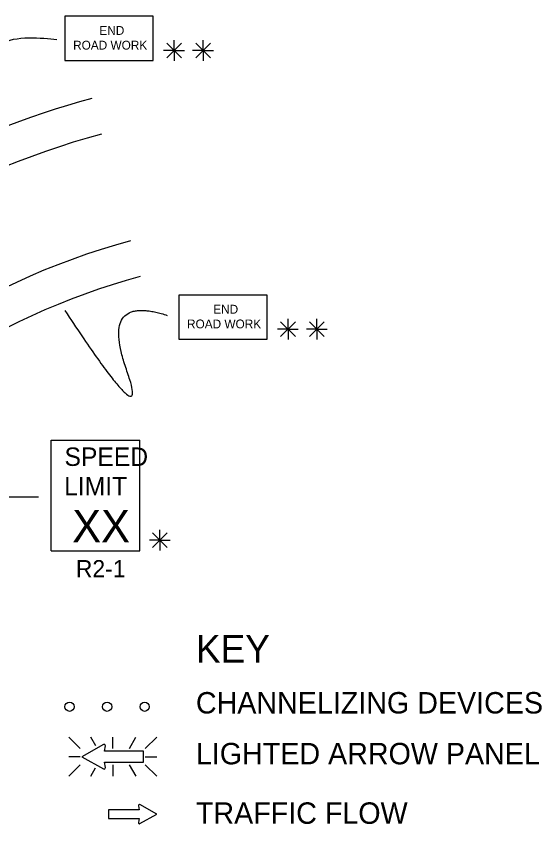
# Model space of a CAD drawing. Extents: x 16728 to 19508, y 5553 to 7079.
# Drawn here: x 17179.3 to 17407.4, y 6484.5 to 6837.4 of the extents above; entities that cross this region are included whole.
import ezdxf

# ---------------------------------------------------------------- set-up
doc = ezdxf.new("R2010")
doc.units = 0
for name, color, linetype in [('MT_SCRATCH_LEVEL_E', 7, 'Continuous'), ('PAVT_EDGE_EX', 7, 'Continuous'), ('TRAFFIC_SIGNS_PR', 7, 'Continuous'), ('TYPICAL_TEXT_DIMEN_EX', 7, 'Continuous'), ('TYPICAL_TEXT_DIMEN_PR', 7, 'Continuous')]:
    doc.layers.add(name, color=color, linetype=linetype)

msp = doc.modelspace()

# ---------------------------------------------------------------- linework, layer by layer
at = {"layer": 'MT_SCRATCH_LEVEL_E'}
for p, q in [((17232.32, 6494.92), (17232.64, 6493.15)), ((17240.25, 6491.29), (17233.01, 6495.4)), ((17232.64, 6493.15), (17219.38, 6493.15)), ((17219.38, 6493.15), (17219.38, 6489.4)), ((17233.01, 6487.15), (17240.25, 6491.29)), ((17219.38, 6489.4), (17232.64, 6489.4)), ((17232.64, 6489.4), (17232.32, 6487.62))]:
    msp.add_line(p, q, dxfattribs=at)
for centre, start, end in [((17232.78, 6495), 60.4248, 189.9638), ((17232.78, 6487.55), 170.0362, 299.7731)]:
    msp.add_arc(centre, 0.463, start, end, dxfattribs=at)
at = {"layer": 'PAVT_EDGE_EX'}
for radius, start, end in [(380, 105.2177, 157.5011), (364, 105.2176, 137.0843), (316, 105.2177, 180), (300, 105.2177, 180)]:
    msp.add_arc((17311.82, 6435.06), radius, start, end, dxfattribs=at)
at = {"layer": 'TRAFFIC_SIGNS_PR'}
for p, q in [((17194.5, 6653.49), (17232.9, 6653.49)), ((17194.5, 6605.49), (17194.5, 6653.49)), ((17232.9, 6605.49), (17232.9, 6653.49)), ((17194.5, 6605.49), (17232.9, 6605.49)), ((17202.1, 6524.68), (17207.03, 6519.75)), ((17213.86, 6520.86), (17211.65, 6524.69)), ((17221.18, 6519.75), (17221.18, 6524.69)), ((17228.42, 6519.75), (17231.27, 6524.69)), ((17235.33, 6519.75), (17240.27, 6524.69)), ((17207.03, 6516.2), (17202.1, 6516.2)), ((17235.33, 6516.2), (17240.27, 6516.2)), ((17202.1, 6507.71), (17207.03, 6512.64)), ((17211.61, 6507.7), (17213.72, 6511.37)), ((17221.18, 6512.64), (17221.18, 6507.7)), ((17231.31, 6507.7), (17228.46, 6512.64)), ((17235.33, 6512.64), (17240.27, 6507.7))]:
    msp.add_line(p, q, dxfattribs=at)
for points in [[(17200.39, 6818.21), (17238.79, 6818.21), (17238.79, 6837.41), (17200.39, 6837.41)], [(17249.82, 6697.28), (17288.22, 6697.28), (17288.22, 6716.48), (17249.82, 6716.48)]]:
    msp.add_lwpolyline(points, close=True, dxfattribs=at)
for points in [[(17217.11, 6521.47), (17207.82, 6516.2), (17217.11, 6510.87)], [(17217.98, 6511.5), (17217.58, 6513.77), (17234.6, 6513.77), (17234.6, 6518.57), (17217.58, 6518.57), (17217.99, 6520.85)]]:
    msp.add_lwpolyline(points, dxfattribs=at)
for centre in [(17202.44, 6537.88), (17218.74, 6537.88), (17235.04, 6537.88)]:
    msp.add_circle(centre, 2, dxfattribs=at)
for centre, radius, start, end in [((17217.4, 6520.95), 0.598, 350.7308, 118.8916), ((17217.4, 6511.4), 0.597, 241.4833, 9.9593)]:
    msp.add_arc(centre, radius, start, end, dxfattribs=at)
at = {"layer": 'TYPICAL_TEXT_DIMEN_PR'}
for p, q in [((17244.63, 6825.78), (17251, 6819.4)), ((17251, 6825.78), (17244.63, 6819.4)), ((17247.81, 6822.59), (17247.81, 6827.04)), ((17263.56, 6825.78), (17257.18, 6819.4)), ((17257.19, 6825.78), (17263.56, 6819.4)), ((17260.37, 6822.59), (17260.37, 6827.04)), ((17247.81, 6822.59), (17243.28, 6822.59)), ((17247.81, 6822.59), (17251, 6822.59)), ((17247.81, 6822.59), (17252.29, 6822.59)), ((17247.81, 6822.59), (17247.81, 6818.09)), ((17260.37, 6822.59), (17255.84, 6822.59)), ((17260.37, 6822.59), (17263.56, 6822.59)), ((17260.37, 6822.59), (17264.85, 6822.59)), ((17260.37, 6822.59), (17260.37, 6818.09)), ((17297.25, 6701.65), (17297.25, 6706.11)), ((17309.81, 6701.65), (17309.81, 6706.11)), ((17297.25, 6701.65), (17292.71, 6701.65)), ((17294.06, 6704.84), (17300.44, 6698.46)), ((17300.44, 6704.84), (17294.06, 6698.46)), ((17297.25, 6701.65), (17300.44, 6701.65)), ((17297.25, 6701.65), (17301.72, 6701.65)), ((17297.25, 6701.65), (17297.25, 6697.15)), ((17309.81, 6701.65), (17305.27, 6701.65)), ((17306.62, 6704.84), (17312.99, 6698.46)), ((17312.99, 6704.84), (17306.62, 6698.46)), ((17309.81, 6701.65), (17312.99, 6701.65)), ((17309.81, 6701.65), (17314.28, 6701.65)), ((17309.81, 6701.65), (17309.81, 6697.15)), ((17170.75, 6628.99), (17189.02, 6628.99)), ((17244.87, 6613.29), (17238.49, 6606.91)), ((17238.5, 6613.29), (17244.87, 6606.91)), ((17241.68, 6610.1), (17241.68, 6614.56)), ((17241.68, 6610.1), (17237.15, 6610.1)), ((17241.68, 6610.1), (17244.87, 6610.1)), ((17241.68, 6610.1), (17246.16, 6610.1)), ((17241.68, 6610.1), (17241.68, 6605.6))]:
    msp.add_line(p, q, dxfattribs=at)
for points, degree in [([(17174.09, 6792.93), (17168.08, 6812.93), (17166.46, 6830.47), (17190.65, 6827.96), (17196.93, 6827.39)], 3), ([(17200.44, 6709.72), (17238.68, 6651.54), (17215.46, 6717.25), (17244.82, 6707.66)], 2)]:
    msp.add_open_spline(points, degree=degree, dxfattribs=at)

# ---------------------------------------------------------------- texts
at = {"layer": 'TRAFFIC_SIGNS_PR'}
for s, height, p in [('END', 3.831, (17215.39, 6829.34)), ('ROAD WORK', 3.831, (17203.99, 6822.96)), ('END', 3.831, (17264.82, 6708.41)), ('ROAD WORK', 3.831, (17253.43, 6702.02)), ('SPEED', 8, (17200.26, 6642.35)), ('LIMIT', 8, (17200.1, 6629.55)), ('XX', 14.031, (17203.61, 6609.25)), ('R2-1', 7.44, (17205.17, 6594.05))]:
    msp.add_text(s, height=height, dxfattribs=at).set_placement(p)
at = {"layer": 'TYPICAL_TEXT_DIMEN_EX'}
for s, height, p in [('KEY', 12, (17257.28, 6556.99)), ('CHANNELIZING DEVICES', 9.3, (17257.28, 6534.94)), ('LIGHTED ARROW PANEL', 9.3, (17257.28, 6512.89)), ('TRAFFIC FLOW', 9.3, (17257.28, 6487.09))]:
    msp.add_text(s, height=height, dxfattribs=at).set_placement(p)

doc.saveas('drawing.dxf')
